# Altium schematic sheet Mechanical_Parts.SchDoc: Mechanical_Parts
size A4; Date: Not used; ApprovedBy: Not used; CheckedBy: Not used; Author: Not used; CompanyName: STMicroelectronics; DrawnBy: Not used; Engineer: Not used; Organization: Not used; Address1: Not used; Address2: Not used; Address3: Not used; Address4: Not used; DocumentNumber: 9; Revision: Not used; SheetNumber: 9; SheetTotal: 9
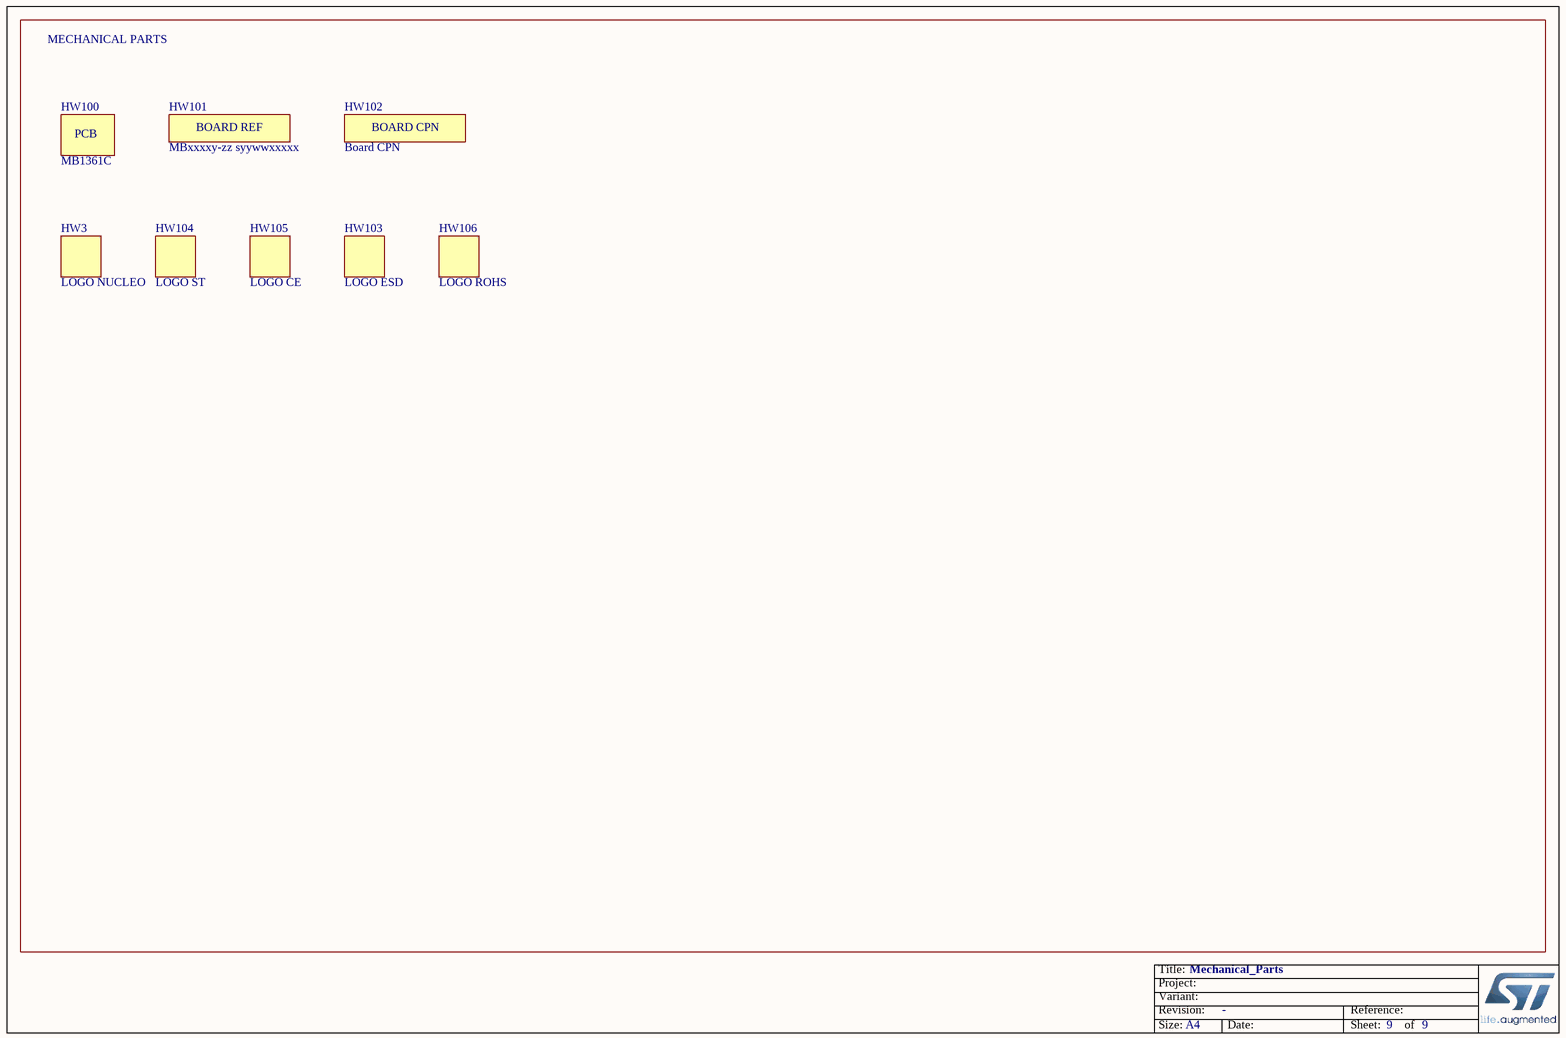
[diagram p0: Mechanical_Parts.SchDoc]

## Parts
HW3  value LOGO NUCLEO  [LOGO_NUCLEO]  (no BOM)
HW100  value MB1361C  (mechanical)
HW101  value MBxxxxy-zz syywwxxxxx  [STICKER_25X9]  (hidden comment: STICKER_BOARD_REF)  (no BOM)
HW102  value Board CPN  [STICKER_25X9]  (hidden comment: STICKER_BOARD_CPN)  (no BOM)
HW103  value LOGO ESD  [LOGO_MAIN_1]  (no BOM)
HW104  value LOGO ST  [LOGO_ST]  (no BOM)
HW105  value LOGO CE  [LOGO_CE]  (no BOM)
HW106  value LOGO ROHS  [LOGO_ROHS]  (no BOM)

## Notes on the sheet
- MECHANICAL PARTS

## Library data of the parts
HW3 = MCD-00636: NUCLEO logo footprint for PCB; Part_Type: Mechanical; Initial_Board_Reference: MB1331
HW100 = MCD-00216: PCB, xxxx for PCB ref, Y for revision; Part_Type: Mechanical; Provided_By: Subcon; Initial_Board_Reference: MB1319
HW101 = MCD-00235: Sticker to mention board reference + serial number; Part_Type: Mechanical; Provided_By: SUBCO
HW102 = MCD-00547: Sticker to mention board CPN code; Part_Type: Mechanical; Provided_By: SUBCO
HW103 = MCD-00627: Hand ESD logo footprint for PCB; Part_Type: Mechanical; Initial_Board_Reference: MB1331
HW104 = MCD-00625: STMicroelectronics logo footprint for PCB; Part_Type: Mechanical; Initial_Board_Reference: MB1331
HW105 = MCD-00626: CE logo footprint for PCB; Part_Type: Mechanical; Initial_Board_Reference: MB1331
HW106 = MCD-00628: ROHS logo footprint for PCB; Part_Type: Mechanical; Initial_Board_Reference: MB1331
